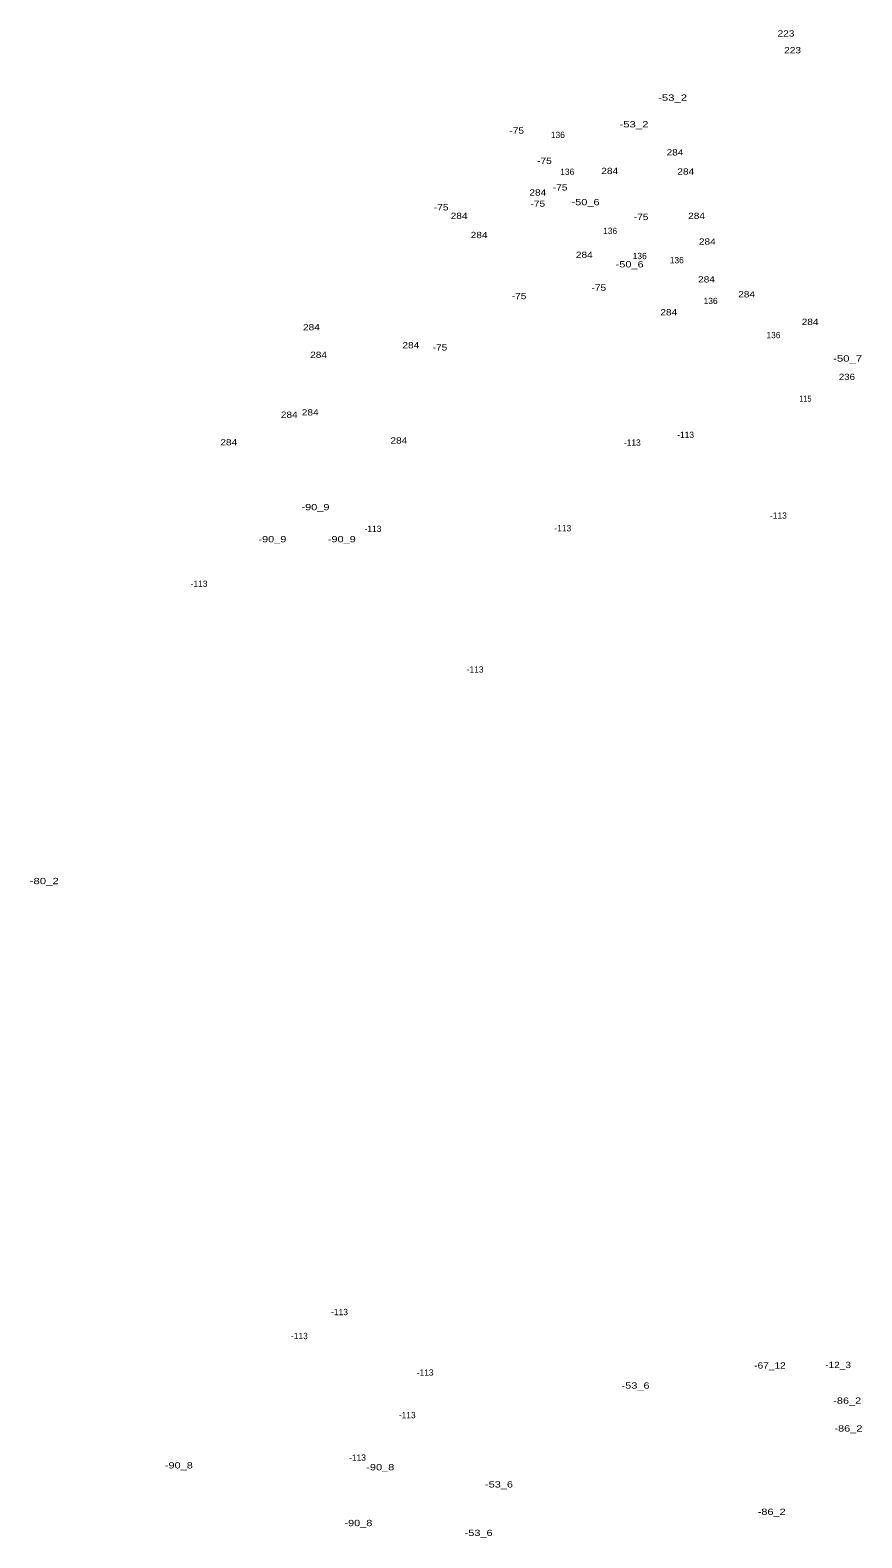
# Model space of a CAD drawing. Extents: x -662996 to -659766, y -998554 to -993949.
# Drawn here: x -662996 to -662467, y -996241 to -995283 of the extents above; entities that cross this region are included whole.
import ezdxf
from ezdxf.enums import TextEntityAlignment as Align

# ---------------------------------------------------------------- set-up
doc = ezdxf.new("R2010")
doc.units = 0
doc.header["$LTSCALE"] = 1.6
doc.layers.add('24', color=7, linetype='Continuous')

msp = doc.modelspace()

# ---------------------------------------------------------------- texts
at = {"layer": '24'}
for s, width, p in [('223', 1.2, (-662515.309, -995286.68)), ('223', 1.2, (-662511.12, -995297.35)), ('-53_2', 1.35, (-662587.429, -995327.52)), ('-75', 1.2, (-662686.551, -995348.48)), ('-53_2', 1.35, (-662611.99, -995344.48)), ('284', 1.2, (-662585.9, -995362.33)), ('-75', 1.2, (-662668.89, -995367.69)), ('284', 1.2, (-662627.41, -995374.14)), ('284', 1.2, (-662579.049, -995374.52)), ('284', 1.2, (-662673.11, -995387.86)), ('-75', 1.2, (-662658.9, -995384.6)), ('-75', 1.2, (-662734.551, -995397.27)), ('-75', 1.2, (-662673.111, -995394.97)), ('-50_6', 1.3, (-662642.75, -995393.97)), ('284', 1.2, (-662723.15, -995402.71)), ('-75', 1.2, (-662607.451, -995403.42)), ('284', 1.2, (-662572.189, -995402.71)), ('284', 1.2, (-662710.429, -995414.9)), ('284', 1.2, (-662565.34, -995419.1)), ('284', 1.2, (-662643.559, -995427.48)), ('-50_6', 1.3, (-662614.72, -995433.53)), ('-75', 1.2, (-662634.331, -995448.36)), ('284', 1.2, (-662565.87, -995443.1)), ('-75', 1.2, (-662685.02, -995453.74)), ('284', 1.2, (-662540.36, -995452.62)), ('284', 1.2, (-662589.86, -995464.05)), ('284', 1.2, (-662817.059, -995473.57)), ('284', 1.2, (-662499.99, -995470.14)), ('284', 1.2, (-662753.84, -995485)), ('-75', 1.2, (-662735.321, -995486.4)), ('284', 1.2, (-662812.49, -995491.1)), ('-50_7', 1.35, (-662476.13, -995493.42)), ('236', 1.15, (-662476.59, -995505.1)), ('115', 0.8, (-662502.99, -995518.99)), ('284', 1.2, (-662831.15, -995529.19)), ('284', 1.2, (-662817.819, -995527.67)), ('284', 1.2, (-662761.459, -995545.57)), ('284', 1.2, (-662869.61, -995546.71)), ('-90_9', 1.3, (-662814.47, -995587.94)), ('-90_9', 1.3, (-662841.87, -995608.35)), ('-90_9', 1.3, (-662797.76, -995608.35)), ('-80_2', 1.35, (-662986.959, -995825.76)), ('-67_12', 1.2, (-662525.52, -996133.84)), ('-12_3', 1.2, (-662482.209, -996133.52)), ('-53_6', 1.3, (-662610.96, -996146.62)), ('-86_2', 1.3, (-662476.41, -996156.22)), ('-86_2', 1.3, (-662475.64, -996173.89)), ('-90_8', 1.3, (-662901.36, -996197.37)), ('-90_8', 1.3, (-662773.26, -996198.53)), ('-53_6', 1.3, (-662697.79, -996209.48)), ('-90_8', 1.3, (-662787.2, -996234.05)), ('-86_2', 1.3, (-662524.41, -996226.9)), ('-53_6', 1.3, (-662710.74, -996240.33))]:
    msp.add_text(s, height=4, dxfattribs=dict(at, width=width)).set_placement(p, align=Align.CENTER)
for s, p in [('136', (-662660.351, -995351.24)), ('136', (-662654.4, -995374.67)), ('136', (-662627.14, -995412.32)), ('136', (-662608.321, -995428.26)), ('136', (-662584.76, -995430.9)), ('136', (-662563.25, -995456.83)), ('136', (-662523.321, -995478.53)), ('-113', (-662579.14, -995541.96)), ('-113', (-662613.03, -995546.91)), ('-113', (-662520.111, -995593.34)), ('-113', (-662777.921, -995601.72)), ('-113', (-662657.211, -995601.34)), ('-113', (-662888.51, -995636.7)), ('-113', (-662712.951, -995691.17)), ('-113', (-662799.171, -996099.87)), ('-113', (-662824.691, -996115.11)), ('-113', (-662744.721, -996138.34)), ('-113', (-662756.14, -996165.39)), ('-113', (-662787.75, -996192.44))]:
    msp.add_text(s, height=4, dxfattribs=at).set_placement(p, align=Align.CENTER)

doc.saveas('drawing.dxf')
